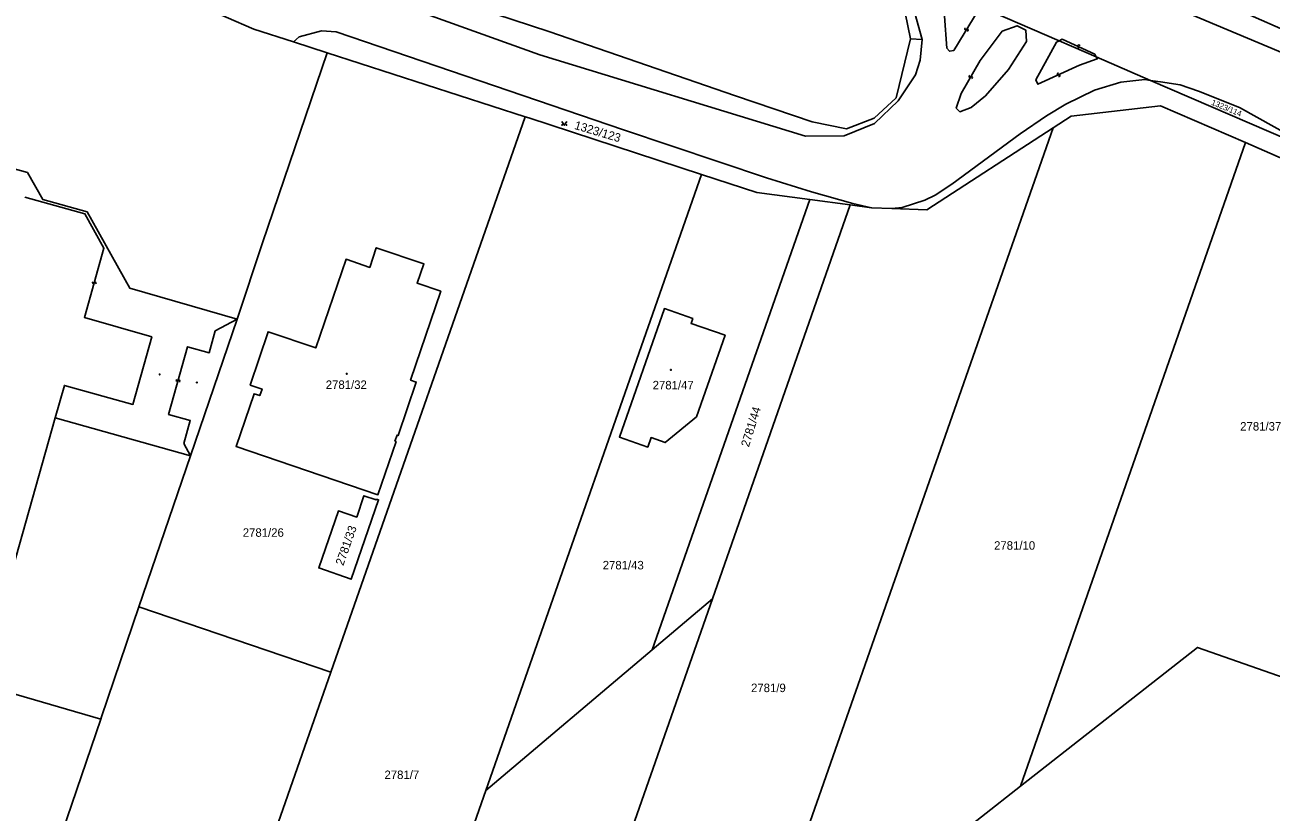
# Model space of a CAD drawing. Extents: x -596024 to -594475, y -1163820 to -1161957.
# Drawn here: x -595298.2 to -595048.9, y -1162214.7 to -1162057.1 of the extents above; entities that cross this region are included whole.
import ezdxf

# ---------------------------------------------------------------- set-up
doc = ezdxf.new("R2010")
doc.units = 0
for name, color, linetype in [('Level 1', 7, 'Continuous'), ('Level 13', 7, 'Continuous'), ('Level 3', 7, 'Continuous'), ('Level 4', 7, 'Continuous'), ('Level 5', 7, 'Continuous'), ('Level 60', 7, 'Continuous'), ('Vrstva 60', 7, 'Continuous')]:
    doc.layers.add(name, color=color, linetype=linetype)

msp = doc.modelspace()

# ---------------------------------------------------------------- linework, layer by layer
at = {"layer": 'Level 1'}
for points in [[(-595323.5, -1161977.39), (-595297.72, -1161986.06), (-595250.7, -1162003.21), (-595195.12, -1162022.75), (-595162.48, -1162033.91), (-595122.07, -1162054.68), (-595121.03, -1162059.9)], [(-595238.8, -1161980.37), (-595132.28, -1162026.69), (-595006.45, -1162079.55)], [(-595330.52, -1162004.87), (-595328.93, -1162006.86), (-595318.38, -1162016.76), (-595243.32, -1162041.99), (-595193.34, -1162058.44), (-595156.06, -1162071.28), (-595140.67, -1162076.52), (-595133.81, -1162077.91), (-595128.32, -1162075.79), (-595123.86, -1162071.67), (-595121.03, -1162059.9)], [(-595130.66, -1162043.29), (-595128.22, -1162044.9), (-595123.67, -1162048.7), (-595120.47, -1162053.53), (-595118.71, -1162060.02)], [(-595285.09, -1162044.31), (-595274.53, -1162048.29), (-595252.35, -1162057.96), (-595244.45, -1162060.5)], [(-595091.31, -1162060.29), (-595107.5, -1162053.29)], [(-595128.82, -1162093.69), (-595132.54, -1162092.82), (-595140.8, -1162090.53), (-595149.82, -1162087.73), (-595178.42, -1162078.09), (-595235.89, -1162058.51), (-595238.84, -1162058.28), (-595243.28, -1162059.45), (-595244.45, -1162060.5)], [(-595244.45, -1162060.5), (-595237.68, -1162062.69)], [(-595118.71, -1162060.02), (-595121.03, -1162059.9)], [(-595083.9, -1162063.49), (-595091.31, -1162060.29)], [(-595237.68, -1162062.69), (-595250.63, -1162100.73), (-595255.68, -1162115.98)], [(-595237.68, -1162062.69), (-595198.1, -1162075.47)], [(-595073.03, -1162068.19), (-595083.9, -1162063.49)], [(-595073.03, -1162068.19), (-595074.18, -1162068.02), (-595078.95, -1162068.55), (-595084.21, -1162070.19), (-595089.99, -1162072.98), (-595093.84, -1162075.29), (-595099.07, -1162078.89), (-595112.78, -1162089), (-595116.11, -1162091.16), (-595118.13, -1162092.19), (-595122.72, -1162093.64), (-595124.78, -1162093.84)], [(-595037.29, -1162083.64), (-595073.03, -1162068.19)], [(-595073.03, -1162068.19), (-595071, -1162068.5), (-595067.11, -1162069.08), (-595063.43, -1162070.37), (-595055.24, -1162073.65), (-595037.29, -1162083.64)], [(-595092.49, -1162077.7), (-595088.91, -1162075.39), (-595071.01, -1162073.26), (-595053.99, -1162080.66)], [(-595198.1, -1162075.47), (-595236.94, -1162186.63)], [(-595162.82, -1162087.02), (-595197.36, -1162075.72), (-595198.1, -1162075.47)], [(-595092.49, -1162077.7), (-595147.56, -1162235)], [(-595124.78, -1162093.84), (-595117.78, -1162094.12), (-595092.49, -1162077.7)], [(-595099, -1162209.49), (-595053.99, -1162080.66)], [(-595053.99, -1162080.66), (-595036.08, -1162088.5), (-595017.86, -1162096.1)], [(-595255.68, -1162115.98), (-595277.18, -1162109.81), (-595285.73, -1162094.54), (-595294.54, -1162092.05), (-595297.65, -1162086.67), (-595307.1, -1162084.06), (-595312.49, -1162087.01), (-595321.47, -1162084.47), (-595339.77, -1162094.82), (-595336.98, -1162099.67)], [(-595205.94, -1162210.31), (-595162.82, -1162087.02)], [(-595141.18, -1162092.05), (-595151.73, -1162090.67), (-595162.82, -1162087.02)], [(-595141.18, -1162092.05), (-595172.71, -1162182.16)], [(-595133.07, -1162093.11), (-595160.66, -1162171.96)], [(-595141.18, -1162092.05), (-595133.07, -1162093.11)], [(-595133.07, -1162093.11), (-595128.82, -1162093.69)], [(-595128.82, -1162093.69), (-595124.78, -1162093.84)], [(-595223.53, -1162139.28), (-595219.87, -1162128.57), (-595221.03, -1162128.18), (-595214.98, -1162110.42), (-595219.73, -1162108.81), (-595218.36, -1162104.91), (-595227.87, -1162101.69), (-595229.17, -1162105.62), (-595233.93, -1162104.01), (-595239.99, -1162121.75), (-595249.5, -1162118.5), (-595253.09, -1162129.2), (-595250.73, -1162130), (-595251.17, -1162131.3), (-595252.31, -1162130.91), (-595255.92, -1162141.49), (-595227.54, -1162151.14), (-595223.92, -1162140.48), (-595224.14, -1162140.4), (-595223.73, -1162139.21), (-595223.53, -1162139.28)], [(-595265.05, -1162143.33), (-595255.68, -1162115.98)], [(-595179.23, -1162139.6), (-595170.26, -1162113.89), (-595164.59, -1162115.89), (-595164.92, -1162116.84), (-595158.1, -1162119.21), (-595163.8, -1162135.53), (-595170.12, -1162140.69), (-595172.9, -1162139.7), (-595173.57, -1162141.6), (-595179.23, -1162139.6)], [(-595339.54, -1162152.29), (-595340.54, -1162155.98), (-595344.6, -1162158.19), (-595347.3, -1162167.65), (-595344.98, -1162171.66), (-595345.4, -1162173.16), (-595343.93, -1162173.56), (-595342.65, -1162175.78), (-595330.22, -1162179.25), (-595328.01, -1162178.03), (-595305.84, -1162184.29), (-595292.09, -1162135.75)], [(-595292.09, -1162135.75), (-595265.05, -1162143.33)], [(-595275.34, -1162173.56), (-595265.05, -1162143.33)], [(-595239.39, -1162165.79), (-595232.91, -1162168.05), (-595227.43, -1162152.15), (-595227.83, -1162152.04), (-595227.87, -1162152.18), (-595230.34, -1162151.35), (-595231.79, -1162155.62), (-595235.45, -1162154.37), (-595239.39, -1162165.79)], [(-595282.98, -1162196.08), (-595282.82, -1162195.56), (-595275.34, -1162173.56)], [(-595275.34, -1162173.56), (-595236.94, -1162186.63)], [(-595197.65, -1162277.66), (-595160.66, -1162171.96)], [(-595172.71, -1162182.16), (-595160.66, -1162171.96)], [(-595350.31, -1162176.47), (-595282.98, -1162196.08)], [(-595172.71, -1162182.16), (-595205.94, -1162210.31)], [(-595099, -1162209.49), (-595063.61, -1162181.68), (-595043.64, -1162188.74)], [(-595236.94, -1162186.63), (-595283.75, -1162320.63)], [(-595282.98, -1162196.08), (-595316.76, -1162295.01)], [(-595205.94, -1162210.31), (-595243.01, -1162316.29)], [(-595153.63, -1162252.41), (-595099, -1162209.49)]]:
    msp.add_lwpolyline(points, dxfattribs=at)
at = {"layer": 'Level 13'}
for centre, start, end in [((-595110, -1162057.93), 96.0235, 328.6135), ((-595109.68, -1162058.13), 276.2379, 148.3359), ((-595087.52, -1162061.64), 192.5865, 64.6845), ((-595087.36, -1162061.3), 12.372, 244.962), ((-595109.14, -1162067.43), 97.4784, 330.0684), ((-595108.82, -1162067.61), 277.6928, 149.7908), ((-595091.48, -1162066.91), 61.9154, 294.0134), ((-595091.32, -1162067.25), 241.701, 114.291), ((-595284.47, -1162108.67), 111.6186, 343.7166), ((-595284.11, -1162108.77), 291.4042, 163.9942), ((-595267.7, -1162128.25), 111.7008, 343.7988), ((-595267.34, -1162128.35), 291.4863, 164.0763)]:
    msp.add_arc(centre, 0.184, start, end, dxfattribs=at)
at = {"layer": 'Level 3'}
for points in [[(-595331.26, -1162007.85), (-595319.54, -1162018.39), (-595195.19, -1162063.06), (-595142.04, -1162079.39), (-595134.3, -1162079.29), (-595128.25, -1162076.82), (-595123.5, -1162072.31), (-595120.01, -1162067.09), (-595119.09, -1162064.15), (-595118.71, -1162060.02)], [(-595107.5, -1162053.29), (-595107.31, -1162053.85), (-595112.36, -1162062.21), (-595113.24, -1162062.38), (-595113.74, -1162061.72), (-595114.23, -1162055.34), (-595116.38, -1162049.73), (-595116.18, -1162049.54)], [(-595102.69, -1162058.36), (-595107.09, -1162064.19), (-595110.88, -1162070.84), (-595111.87, -1162073.75), (-595111.15, -1162074.47), (-595108.9, -1162073.64), (-595106.04, -1162071.28), (-595101.43, -1162066), (-595097.8, -1162060.4), (-595097.97, -1162058.14), (-595099.72, -1162057.26), (-595102.69, -1162058.36)], [(-595091.31, -1162060.29), (-595091.81, -1162060.56), (-595095.99, -1162068.09), (-595095.55, -1162068.97), (-595087.25, -1162065.18), (-595083.68, -1162063.91), (-595083.9, -1162063.49)], [(-595083.9, -1162063.49), (-595084.17, -1162062.98), (-595090.71, -1162059.96), (-595091.31, -1162060.29)], [(-595292.09, -1162135.75), (-595290.26, -1162129.26), (-595276.56, -1162133.06), (-595272.79, -1162119.56), (-595286.25, -1162115.65), (-595282.34, -1162101.79), (-595286.14, -1162094.94), (-595298.15, -1162091.58)], [(-595265.05, -1162143.33), (-595266.37, -1162140.9), (-595265.08, -1162136.29), (-595269.43, -1162135.09), (-595265.62, -1162121.51), (-595261.28, -1162122.72), (-595260.07, -1162118.36), (-595255.68, -1162115.98)]]:
    msp.add_lwpolyline(points, dxfattribs=at)
at = {"layer": 'Level 5'}
msp.add_lwpolyline([(-595190.77, -1162076.43), (-595190.27, -1162077.18), (-595189.77, -1162076.43)], dxfattribs=at)
for centre, radius in [((-595190.72, -1162077.13), 0.05), ((-595189.82, -1162077.13), 0.05), ((-595168.94, -1162126.16), 0.09), ((-595168.94, -1162126.16), 0.0521), ((-595271.2, -1162127.05), 0.09), ((-595271.2, -1162127.05), 0.0521), ((-595263.75, -1162128.67), 0.09), ((-595263.75, -1162128.67), 0.0521), ((-595233.79, -1162126.93), 0.09), ((-595233.79, -1162126.93), 0.0521)]:
    msp.add_circle(centre, radius, dxfattribs=at)
at = {"layer": 'Level 60'}
for points in [[(-595323.5, -1161977.39), (-595297.72, -1161986.06), (-595250.7, -1162003.21), (-595195.12, -1162022.75), (-595162.48, -1162033.91), (-595122.07, -1162054.68), (-595121.03, -1162059.9), (-595123.86, -1162071.67), (-595128.32, -1162075.79), (-595133.81, -1162077.91), (-595140.67, -1162076.52), (-595156.06, -1162071.28), (-595193.34, -1162058.44), (-595243.32, -1162041.99), (-595318.38, -1162016.76), (-595328.93, -1162006.86), (-595330.52, -1162004.87), (-595329.7, -1162001.47), (-595327.37, -1161992.6), (-595325.35, -1161984.26)], [(-595238.8, -1161980.37), (-595237.73, -1161978.08), (-595169.27, -1162007.29), (-595152.08, -1162009.88), (-595134.47, -1162015.68), (-595105.38, -1162031.41), (-595102.13, -1162032.23), (-595097.98, -1162031.92), (-595094.59, -1162030.35), (-595092.68, -1162027.63), (-595084.11, -1162034.15), (-595084.28, -1162038.43), (-595082.35, -1162041), (-595075.19, -1162044.31), (-595061.42, -1162051.37), (-595051.87, -1162055.71), (-595032.44, -1162064.2), (-595025.05, -1162067.99), (-595005.99, -1162078.48), (-595006.45, -1162079.55), (-595132.28, -1162026.69)], [(-595140.8, -1162090.53), (-595132.54, -1162092.82), (-595128.82, -1162093.69), (-595133.07, -1162093.11), (-595141.18, -1162092.05), (-595151.73, -1162090.67), (-595162.82, -1162087.02), (-595197.36, -1162075.72), (-595198.1, -1162075.47), (-595237.68, -1162062.69), (-595244.45, -1162060.5), (-595243.28, -1162059.45), (-595238.84, -1162058.28), (-595235.89, -1162058.51), (-595178.42, -1162078.09), (-595149.82, -1162087.73)], [(-595250.63, -1162100.73), (-595237.68, -1162062.69), (-595198.1, -1162075.47), (-595236.94, -1162186.63), (-595275.34, -1162173.56), (-595265.05, -1162143.33), (-595255.68, -1162115.98)], [(-595037.29, -1162083.64), (-595073.03, -1162068.19), (-595071, -1162068.5), (-595067.11, -1162069.08), (-595063.43, -1162070.37), (-595055.24, -1162073.65)], [(-595092.49, -1162077.7), (-595088.91, -1162075.39), (-595071.01, -1162073.26), (-595053.99, -1162080.66), (-595099, -1162209.49), (-595153.63, -1162252.41), (-595147.56, -1162235)], [(-595197.36, -1162075.72), (-595162.82, -1162087.02), (-595205.94, -1162210.31), (-595243.01, -1162316.29), (-595247.55, -1162329.41), (-595254.69, -1162350.01), (-595261.65, -1162342.31), (-595271.68, -1162331.19), (-595283.75, -1162320.63), (-595236.94, -1162186.63), (-595198.1, -1162075.47)], [(-595133.07, -1162093.11), (-595128.82, -1162093.69), (-595124.78, -1162093.84), (-595117.78, -1162094.12), (-595092.49, -1162077.7), (-595147.56, -1162235), (-595197.65, -1162277.66), (-595160.66, -1162171.96)], [(-595018.56, -1162097.71), (-595015.75, -1162098.9), (-595015.05, -1162097.27), (-595012.11, -1162098.5), (-595043.64, -1162188.74), (-595063.61, -1162181.68), (-595099, -1162209.49), (-595053.99, -1162080.66), (-595036.08, -1162088.5), (-595017.86, -1162096.1)], [(-595141.18, -1162092.05), (-595172.71, -1162182.16), (-595205.94, -1162210.31), (-595162.82, -1162087.02), (-595151.73, -1162090.67)], [(-595172.71, -1162182.16), (-595141.18, -1162092.05), (-595133.07, -1162093.11), (-595160.66, -1162171.96)], [(-595223.53, -1162139.28), (-595219.87, -1162128.57), (-595221.03, -1162128.18), (-595214.98, -1162110.42), (-595219.73, -1162108.81), (-595218.36, -1162104.91), (-595227.87, -1162101.69), (-595229.17, -1162105.62), (-595233.93, -1162104.01), (-595239.99, -1162121.75), (-595249.5, -1162118.5), (-595253.09, -1162129.2), (-595250.73, -1162130), (-595251.17, -1162131.3), (-595252.31, -1162130.91), (-595255.92, -1162141.49), (-595227.54, -1162151.14), (-595223.92, -1162140.48), (-595224.14, -1162140.4), (-595223.73, -1162139.21)], [(-595219.87, -1162128.57), (-595223.53, -1162139.28), (-595223.73, -1162139.21), (-595224.14, -1162140.4), (-595223.92, -1162140.48), (-595227.54, -1162151.14), (-595255.92, -1162141.49), (-595252.31, -1162130.91), (-595251.17, -1162131.3), (-595250.73, -1162130), (-595253.09, -1162129.2), (-595249.5, -1162118.5), (-595239.99, -1162121.75), (-595233.93, -1162104.01), (-595229.17, -1162105.62), (-595227.87, -1162101.69), (-595218.36, -1162104.91), (-595219.73, -1162108.81), (-595214.98, -1162110.42), (-595221.03, -1162128.18)], [(-595170.26, -1162113.89), (-595179.23, -1162139.6), (-595173.57, -1162141.6), (-595172.9, -1162139.7), (-595170.12, -1162140.69), (-595163.8, -1162135.53), (-595158.1, -1162119.21), (-595164.92, -1162116.84), (-595164.59, -1162115.89)], [(-595179.23, -1162139.6), (-595170.26, -1162113.89), (-595164.59, -1162115.89), (-595164.92, -1162116.84), (-595158.1, -1162119.21), (-595163.8, -1162135.53), (-595170.12, -1162140.69), (-595172.9, -1162139.7), (-595173.57, -1162141.6)], [(-595239.39, -1162165.79), (-595232.91, -1162168.05), (-595227.43, -1162152.15), (-595227.83, -1162152.04), (-595227.87, -1162152.18), (-595230.34, -1162151.35), (-595231.79, -1162155.62), (-595235.45, -1162154.37)], [(-595232.91, -1162168.05), (-595239.39, -1162165.79), (-595235.45, -1162154.37), (-595231.79, -1162155.62), (-595230.34, -1162151.35), (-595227.87, -1162152.18), (-595227.83, -1162152.04), (-595227.43, -1162152.15)], [(-595283.75, -1162320.63), (-595297.27, -1162308.67), (-595316.76, -1162295.01), (-595282.98, -1162196.08), (-595282.82, -1162195.56), (-595275.34, -1162173.56), (-595236.94, -1162186.63)], [(-595197.65, -1162277.66), (-595243.01, -1162316.29), (-595205.94, -1162210.31), (-595172.71, -1162182.16), (-595160.66, -1162171.96)], [(-595341.8, -1162190.17), (-595353.12, -1162186.95), (-595350.31, -1162176.47), (-595282.98, -1162196.08), (-595316.76, -1162295.01), (-595349.09, -1162276.45), (-595374, -1162262.8), (-595372.41, -1162256.53), (-595355.74, -1162261.1), (-595354.35, -1162256.23), (-595351.24, -1162254), (-595331.37, -1162259.42), (-595328.22, -1162248.41), (-595323.28, -1162249.7), (-595314.64, -1162218.5), (-595319.47, -1162217.13), (-595315.78, -1162204.23), (-595337.5, -1162198.13), (-595338.22, -1162196.92), (-595336.74, -1162191.51)], [(-594995.35, -1162400.36), (-594996.96, -1162405.12), (-595059.52, -1162377.94), (-595070.96, -1162372.97), (-595103.12, -1162359), (-595144.9, -1162340.85), (-595179.27, -1162325.92), (-595209.84, -1162312.64), (-595223.01, -1162306.92), (-595202.13, -1162290.51), (-595153.63, -1162252.41), (-595099, -1162209.49), (-595063.61, -1162181.68), (-595043.64, -1162188.74), (-595010.66, -1162200.4), (-595002.31, -1162203.35), (-595014.61, -1162238.14), (-594977.25, -1162251.35), (-594987.53, -1162275.68), (-594958, -1162288.15), (-594958.93, -1162290.91), (-594971.51, -1162330.56), (-594979.52, -1162353.85), (-594987.48, -1162377.12)]]:
    msp.add_lwpolyline(points, close=True, dxfattribs=at)
for points in [[(-595300.3, -1162039.1), (-595285.09, -1162044.31), (-595274.53, -1162048.29), (-595252.35, -1162057.96), (-595244.45, -1162060.5), (-595237.68, -1162062.69), (-595250.63, -1162100.73), (-595255.68, -1162115.98), (-595277.18, -1162109.81), (-595285.73, -1162094.54), (-595294.54, -1162092.05), (-595297.65, -1162086.67), (-595307.1, -1162084.06)], [(-595243.32, -1162041.99), (-595193.34, -1162058.44), (-595156.06, -1162071.28), (-595140.67, -1162076.52), (-595133.81, -1162077.91), (-595128.32, -1162075.79), (-595123.86, -1162071.67), (-595121.03, -1162059.9), (-595118.71, -1162060.02), (-595120.47, -1162053.53)], [(-595107.5, -1162053.29), (-595091.31, -1162060.29), (-595083.9, -1162063.49), (-595073.03, -1162068.19), (-595074.18, -1162068.02), (-595078.95, -1162068.55), (-595084.21, -1162070.19), (-595089.99, -1162072.98), (-595093.84, -1162075.29), (-595099.07, -1162078.89), (-595112.78, -1162089), (-595116.11, -1162091.16), (-595118.13, -1162092.19), (-595122.72, -1162093.64), (-595124.78, -1162093.84), (-595128.82, -1162093.69), (-595132.54, -1162092.82), (-595140.8, -1162090.53), (-595149.82, -1162087.73), (-595178.42, -1162078.09), (-595235.89, -1162058.51), (-595238.84, -1162058.28), (-595243.28, -1162059.45), (-595244.45, -1162060.5), (-595252.35, -1162057.96), (-595274.53, -1162048.29)], [(-595036.08, -1162088.5), (-595053.99, -1162080.66), (-595071.01, -1162073.26), (-595088.91, -1162075.39), (-595092.49, -1162077.7), (-595117.78, -1162094.12), (-595124.78, -1162093.84), (-595122.72, -1162093.64), (-595118.13, -1162092.19), (-595116.11, -1162091.16), (-595112.78, -1162089), (-595099.07, -1162078.89), (-595093.84, -1162075.29), (-595089.99, -1162072.98), (-595084.21, -1162070.19), (-595078.95, -1162068.55), (-595074.18, -1162068.02), (-595073.03, -1162068.19), (-595037.29, -1162083.64)], [(-595307.1, -1162084.06), (-595297.65, -1162086.67), (-595294.54, -1162092.05), (-595285.73, -1162094.54), (-595277.18, -1162109.81), (-595255.68, -1162115.98), (-595265.05, -1162143.33), (-595292.09, -1162135.75), (-595305.84, -1162184.29)], [(-595305.84, -1162184.29), (-595292.09, -1162135.75), (-595265.05, -1162143.33), (-595275.34, -1162173.56), (-595282.82, -1162195.56), (-595282.98, -1162196.08), (-595350.31, -1162176.47)]]:
    msp.add_lwpolyline(points, dxfattribs=at)
at = {"layer": 'Vrstva 60'}
for points in [[(-595006.45, -1162079.55), (-595132.28, -1162026.69), (-595238.8, -1161980.37), (-595292.83, -1161956.88), (-595324.53, -1161956.88), (-595320.66, -1161958.55), (-595160.16, -1162028.09), (-595147.05, -1162034.46), (-595133.66, -1162041.3), (-595130.66, -1162043.29), (-595116.18, -1162049.54), (-595107.5, -1162053.29), (-595091.31, -1162060.29), (-595083.9, -1162063.49), (-595073.03, -1162068.19), (-595071, -1162068.5), (-595067.11, -1162069.08), (-595063.43, -1162070.37), (-595055.24, -1162073.65), (-595037.29, -1162083.64)], [(-595323.5, -1161977.39), (-595297.72, -1161986.06), (-595250.7, -1162003.21), (-595195.12, -1162022.75), (-595162.48, -1162033.91), (-595122.07, -1162054.68), (-595121.03, -1162059.9), (-595118.71, -1162060.02), (-595120.47, -1162053.53), (-595123.67, -1162048.7), (-595128.22, -1162044.9), (-595130.66, -1162043.29), (-595161.24, -1162030.07), (-595279.23, -1161978.8), (-595319.7, -1161962.54)]]:
    msp.add_lwpolyline(points, dxfattribs=at)

# ---------------------------------------------------------------- texts
at = {"layer": 'Level 4'}
for s, height, rotation, p in [('1323/114', 1.14, 337.5123, (-595060.96, -1162073.04)), ('1323/123', 1.7, 343.3904, (-595188.37, -1162077.89)), ('2781/44', 1.7, 72.8, (-595153.36, -1162141.7)), ('2781/33', 1.7, 70.56, (-595234.48, -1162165.44))]:
    msp.add_text(s, height=height, rotation=rotation, dxfattribs=at).set_placement(p)
for s, p in [('2781/32', (-595237.98, -1162129.96)), ('2781/47', (-595172.6, -1162130.05)), ('2781/37', (-595055.08, -1162138.29)), ('2781/26', (-595254.58, -1162159.55)), ('2781/10', (-595104.31, -1162162.14)), ('2781/43', (-595182.59, -1162166.08)), ('2781/9', (-595152.92, -1162190.64)), ('2781/7', (-595226.24, -1162208.04))]:
    msp.add_text(s, height=1.7, dxfattribs=at).set_placement(p)

doc.saveas('drawing.dxf')
